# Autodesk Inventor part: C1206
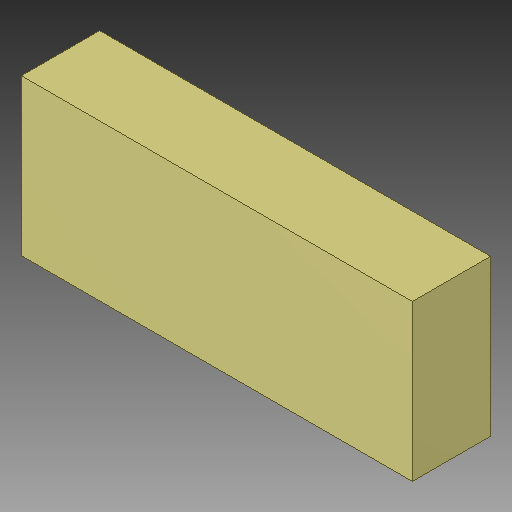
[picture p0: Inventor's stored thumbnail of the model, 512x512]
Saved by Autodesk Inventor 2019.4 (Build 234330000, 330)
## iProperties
Created: 2019-11
Part Number: C1206
Material: Generic
Document SubType Name: Modeling
Designer: Willist
Density: 1 g/cm^3
Appearance: C1206, C1206
Author: Willist
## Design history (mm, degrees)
sketch "C1206, C1206_11"
  geometry: L1 (-2.498, 1.008)-(2.498, 1.008); L2 (2.498, 1.008)-(2.498, -0.983); L3 (2.498, -0.983)-(-2.498, -0.983); L4 (-2.498, -0.983)-(-2.498, 1.008)
  constraints: 8 end point
extrude "Extrusion1" join sketch "C1206, C1206_11" distance "d0" = 1; taper "d1" = 0 deg
body "Solid1"
